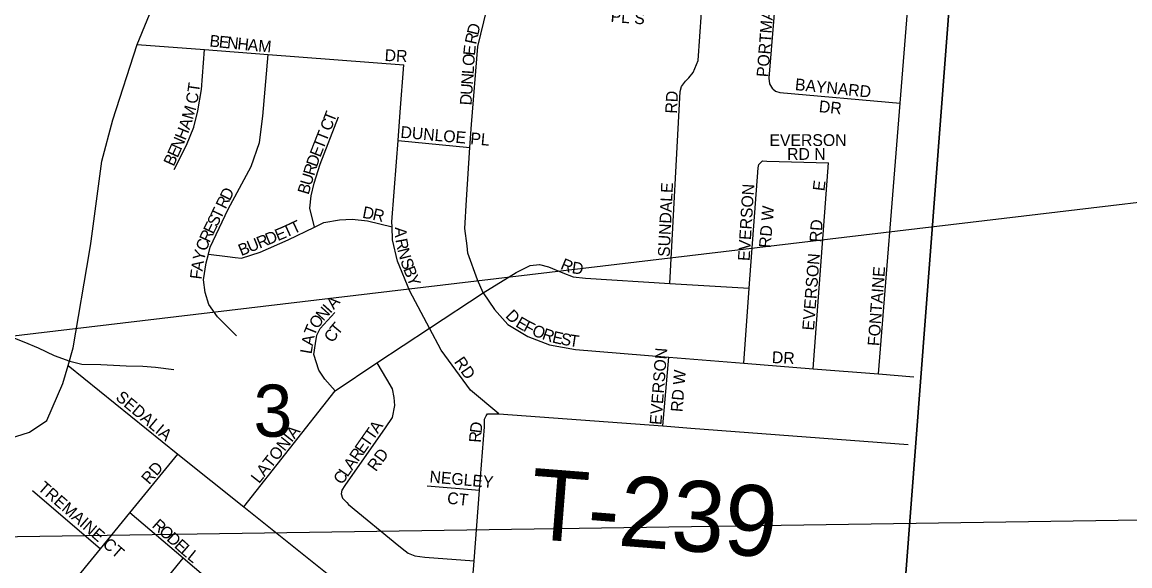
# Model space of a CAD drawing. Extents: x 0 to 34, y 0 to 22.
# Drawn here: x 7.534 to 8.423, y 17.345 to 17.781 of the extents above; entities that cross this region are included whole.
import ezdxf

# ---------------------------------------------------------------- set-up
doc = ezdxf.new("R2010")
doc.units = 0
for name, color, linetype in [('BD_P_Text', 7, 'Continuous'), ('GM_X_County_Road', 7, 'Continuous'), ('GM_X_Minor_River', 7, 'Continuous'), ('GM_X_Section', 7, 'Continuous'), ('GM_X_Section_Text', 7, 'Continuous'), ('GM_X_Township_Road', 7, 'Continuous'), ('GM_X_Township_Road_Text', 7, 'Continuous'), ('GM_X_Township_Subdivision', 7, 'Continuous'), ('GM_X_Township_Subdivision_Text', 7, 'Continuous')]:
    doc.layers.add(name, color=color, linetype=linetype)

msp = doc.modelspace()

# ---------------------------------------------------------------- linework, layer by layer
at = {"layer": 'BD_P_Text'}
msp.add_lwpolyline([(9.7485, 17.79308), (5.97867, 17.34543), (9.7485, 17.40141)], close=True, dxfattribs=at)
at = {"layer": 'GM_X_County_Road'}
for points in [[(7.58898, 17.60376), (7.58928, 17.60553), (7.59778, 17.66988), (7.6066, 17.70308), (7.62629, 17.76361), (7.65462, 17.83269), (7.66454, 17.86111), (7.67094, 17.88135), (7.67231, 17.90988)], [(7.20767, 17.30576), (7.22006, 17.35497), (7.22615, 17.36156), (7.23071, 17.36815), (7.2373, 17.37474), (7.25809, 17.39604), (7.28242, 17.41175), (7.30574, 17.42341), (7.34934, 17.43405), (7.48925, 17.44926), (7.52376, 17.44731), (7.53981, 17.45222), (7.55371, 17.46174), (7.56661, 17.49141), (7.57076, 17.5057), (7.57493, 17.52006), (7.58785, 17.59698), (7.58898, 17.60376)]]:
    msp.add_lwpolyline(points, dxfattribs=at)
at = {"layer": 'GM_X_Minor_River'}
msp.add_lwpolyline([(7.52385, 17.52935), (7.53517, 17.52472), (7.54686, 17.5201), (7.55968, 17.51395), (7.57213, 17.50932), (7.58195, 17.50698), (7.59707, 17.50651), (7.61749, 17.50563), (7.63072, 17.50517), (7.64092, 17.50435), (7.65566, 17.50274)], dxfattribs=at)
at = {"layer": 'GM_X_Section'}
for points in [[(7.25608, 17.99704), (7.7594, 17.95531), (8.26119, 17.91328), (8.28732, 17.91243), (8.21553, 16.97509), (7.19182, 17.04453)], [(8.28732, 17.91243), (8.78533, 17.87214), (9.29851, 17.83319), (9.21917, 16.9042), (8.21553, 16.97509)]]:
    msp.add_lwpolyline(points, close=True, dxfattribs=at)
at = {"layer": 'GM_X_Township_Road'}
for points in [[(7.91657, 17.46715), (8.04831, 17.45728), (8.0706, 17.45561), (8.0706, 17.45561)], [(8.0706, 17.45561), (8.24517, 17.44253)]]:
    msp.add_lwpolyline(points, dxfattribs=at)
at = {"layer": 'GM_X_Township_Subdivision'}
for points in [[(7.90411, 17.56419), (7.89935, 17.57452), (7.89173, 17.59591), (7.89107, 17.602), (7.8894, 17.6157), (7.89053, 17.63885), (7.89332, 17.68094), (7.89454, 17.69917), (7.89971, 17.76176), (7.90926, 17.80167), (7.92328, 17.84308), (7.945, 17.89819), (7.96341, 17.93943), (7.96608, 17.94542)], [(8.22144, 17.49905), (8.23877, 17.71644), (8.24732, 17.8237), (8.25217, 17.87646), (8.25174, 17.88662), (8.25005, 17.90439), (8.2509, 17.92059)], [(8.05394, 17.57175), (8.06211, 17.72575), (8.06332, 17.72991), (8.06642, 17.73403), (8.06912, 17.73665), (8.0726, 17.74115), (8.07654, 17.75059), (8.07937, 17.78927), (8.08318, 17.84124), (8.08626, 17.88336), (8.08428, 17.88993), (8.0845, 17.89175), (8.08145, 17.89996)], [(8.13644, 17.72798), (8.13423, 17.73181), (8.13355, 17.73638), (8.14576, 17.88279), (8.14694, 17.88543)], [(7.62629, 17.76361), (7.68026, 17.75946), (7.73133, 17.75552), (7.84035, 17.74714)], [(7.65592, 17.6631), (7.66571, 17.68269), (7.67163, 17.69704), (7.67488, 17.71028), (7.6778, 17.72732), (7.68026, 17.75946)], [(7.70608, 17.52976), (7.69078, 17.54481), (7.68374, 17.5548), (7.68086, 17.56434), (7.67951, 17.57461), (7.68162, 17.58825), (7.6834, 17.59511), (7.68485, 17.60074), (7.69938, 17.63127), (7.70837, 17.64821), (7.71774, 17.66553), (7.7245, 17.68479), (7.72711, 17.70602), (7.73133, 17.75552)], [(7.91657, 17.46715), (7.89375, 17.48612), (7.87039, 17.51802), (7.86089, 17.53579), (7.845, 17.56552), (7.83516, 17.5896), (7.83126, 17.60676), (7.83089, 17.61707), (7.83074, 17.6212), (7.83454, 17.66937), (7.83579, 17.68643), (7.83746, 17.7092), (7.84035, 17.74714)], [(8.13644, 17.72798), (8.13868, 17.72605), (8.14208, 17.72485), (8.23877, 17.71644)], [(7.76868, 17.6169), (7.76496, 17.63212), (7.76588, 17.64198), (7.76832, 17.65219), (7.77311, 17.66731), (7.78775, 17.70544)], [(7.83579, 17.68643), (7.89332, 17.68094)], [(8.11316, 17.50774), (8.11764, 17.56795), (8.1248, 17.66436), (8.12535, 17.6672), (8.12831, 17.67)], [(8.12831, 17.67), (8.13162, 17.66971), (8.18135, 17.6684)], [(8.16882, 17.50327), (8.18135, 17.6684)], [(7.6834, 17.59511), (7.69876, 17.5933), (7.70481, 17.59244), (7.71011, 17.59197), (7.72497, 17.59668), (7.74749, 17.60657), (7.76868, 17.6169), (7.77615, 17.62054), (7.78869, 17.62263), (7.79893, 17.62322), (7.81104, 17.62189), (7.83089, 17.61707)], [(7.7118, 17.39237), (7.78524, 17.48545), (7.81867, 17.50805), (7.86089, 17.53579), (7.90411, 17.56419), (7.93053, 17.58049), (7.9416, 17.586), (7.9492, 17.58702), (7.95637, 17.58501), (7.96804, 17.58027), (7.97633, 17.57709), (7.98617, 17.5758), (8.05394, 17.57175), (8.11764, 17.56795)], [(7.90411, 17.56419), (7.91299, 17.55076), (7.92379, 17.53882), (7.93993, 17.52906), (7.95726, 17.52232), (7.97804, 17.51858), (8.05298, 17.51256), (8.11316, 17.50774), (8.16882, 17.50327), (8.22144, 17.49905), (8.24984, 17.49677)], [(7.78524, 17.48545), (7.77677, 17.49482), (7.77196, 17.50212), (7.768, 17.51471), (7.76927, 17.52343), (7.77052, 17.53025), (7.77326, 17.53552), (7.78484, 17.54825)], [(8.04831, 17.45728), (8.05298, 17.51256)], [(7.57076, 17.5057), (7.65892, 17.43461), (7.7118, 17.39237), (7.80817, 17.3154), (7.83868, 17.29103), (7.84924, 17.28744), (7.89162, 17.28422), (8.17216, 17.26292), (8.1911, 17.26186), (8.20059, 17.26323), (8.21734, 17.26789), (8.22687, 17.27078), (8.23682, 17.27708), (8.2491, 17.28638), (8.25601, 17.29159), (8.26518, 17.29638), (8.2759, 17.30304), (8.29359, 17.31871)], [(7.81867, 17.50805), (7.82643, 17.49479), (7.83085, 17.48712), (7.83226, 17.48026), (7.83291, 17.4738), (7.83086, 17.46396), (7.82541, 17.45569), (7.79284, 17.4095), (7.7905, 17.40573), (7.79007, 17.4027), (7.79115, 17.39927), (7.79451, 17.3958), (7.796, 17.39425), (7.8364, 17.36094), (7.84127, 17.35707), (7.84389, 17.35513), (7.84916, 17.35314), (7.8571, 17.35188), (7.89665, 17.34891)], [(7.89162, 17.28422), (7.89665, 17.34891), (7.90108, 17.40585), (7.90503, 17.4567), (7.90513, 17.46277), (7.90631, 17.46541), (7.90747, 17.46691), (7.91657, 17.46715)], [(7.54485, 17.12154), (7.54917, 17.17842), (7.55737, 17.2864), (7.56025, 17.30079), (7.56361, 17.31139), (7.57168, 17.32795), (7.59686, 17.35873), (7.62042, 17.38754), (7.65892, 17.43461)], [(7.54223, 17.40551), (7.59686, 17.35873)], [(7.85916, 17.4092), (7.90108, 17.40585)], [(7.74685, 17.09652), (7.7516, 17.15869), (7.75502, 17.20349), (7.75477, 17.21147), (7.75156, 17.22368), (7.73097, 17.28667), (7.72842, 17.29316), (7.72135, 17.30163), (7.66326, 17.35108), (7.62042, 17.38754)], [(7.59917, 17.17384), (7.60832, 17.20241), (7.61036, 17.21188), (7.61286, 17.22551), (7.61551, 17.24863), (7.61792, 17.28087), (7.61995, 17.2892), (7.62427, 17.29863), (7.63083, 17.3087), (7.64176, 17.32493), (7.66326, 17.35108)]]:
    msp.add_lwpolyline(points, dxfattribs=at)

# ---------------------------------------------------------------- texts
at = {"layer": 'GM_X_Section_Text'}
msp.add_text('3', height=0.04186, rotation=0.00001, dxfattribs=at).set_placement((7.71965, 17.44863))
at = {"layer": 'GM_X_Township_Road_Text'}
msp.add_text('T-239', height=0.056818, rotation=355.5173, dxfattribs=at).set_placement((7.94, 17.36694))
at = {"layer": 'GM_X_Township_Subdivision_Text'}
for s, height, rotation, p in [('PORTMAN DR', 0.00947, 85.60129, (8.13287, 17.73704)), ('PL S', 0.00947, 355.76599, (8.00607, 17.7816)), ('D', 0.00947, 75.97147, (7.89992, 17.77034)), ('B', 0.00947, 354.06471, (7.684, 17.76197)), ('E', 0.00947, 354.04543, (7.69146, 17.7612)), ('N', 0.00947, 354.05611, (7.69809, 17.7605)), ('H', 0.00947, 354.05611, (7.70638, 17.75964)), ('A', 0.00947, 354.05611, (7.71467, 17.75878)), ('M', 0.00947, 355.0481, (7.72313, 17.7579)), ('R', 0.00947, 77.66285, (7.89833, 17.76308)), ('DR', 0.00947, 356.98842, (7.82474, 17.75031)), ('E', 0.00947, 84.4284, (7.89734, 17.75427)), ('O', 0.00947, 86.11978, (7.89678, 17.74603)), ('L', 0.00947, 86.11978, (7.89633, 17.73938)), ('CT', 0.00947, 81.87711, (7.67455, 17.71545)), ('U', 0.00947, 86.11978, (7.89521, 17.72275)), ('N', 0.00947, 86.11978, (7.89577, 17.73106)), ('BAYNARD', 0.00947, 354.20725, (8.15399, 17.72697)), ('D', 0.00947, 86.11978, (7.89464, 17.71444)), ('RD', 0.00947, 86.97755, (8.05953, 17.70783)), ('M', 0.00947, 73.53902, (7.67088, 17.70269)), ('DR', 0.00947, 353.99459, (8.17315, 17.70931)), ('T', 0.00947, 68.57406, (7.78418, 17.70034)), ('H', 0.00947, 67.96825, (7.6649, 17.68607)), ('A', 0.00947, 72.32694, (7.66828, 17.69454)), ('C', 0.00947, 68.5834, (7.78144, 17.69336)), ('DUNLOE PL', 0.00947, 354.80557, (7.83731, 17.68868)), ('N', 0.00947, 66.36465, (7.66144, 17.67817)), ('T', 0.00947, 68.57406, (7.77566, 17.67862)), ('T', 0.00947, 68.60243, (7.7781, 17.68483)), ('EVERSON', 0.00947, 0.00001, (8.13381, 17.68202)), ('E', 0.00947, 65.59595, (7.65863, 17.67197)), ('E', 0.00947, 68.69574, (7.77324, 17.67241)), ('RD N', 0.00947, 0.00001, (8.14798, 17.6709)), ('B', 0.00947, 65.58619, (7.65553, 17.66514)), ('D', 0.00947, 70.38293, (7.77047, 17.66463)), ('U', 0.00947, 73.23795, (7.76593, 17.64959)), ('R', 0.00947, 73.17047, (7.76833, 17.65757)), ('B', 0.00947, 73.24725, (7.76377, 17.64241)), ('SUNDALE', 0.00947, 87.35564, (8.05369, 17.59282)), ('E', 0.00947, 82.87834, (8.17788, 17.64545)), ('D', 0.00947, 63.84277, (7.70058, 17.63754)), ('EVERSON', 0.00947, 86.42557, (8.11787, 17.58951)), ('T', 0.00947, 63.85048, (7.69323, 17.62258)), ('R', 0.00947, 63.83384, (7.69727, 17.63081)), ('D', 0.00947, 348.98156, (7.80654, 17.6245)), ('RD W', 0.00947, 85.23886, (8.13477, 17.59988)), ('S', 0.00947, 63.85264, (7.69029, 17.6166)), ('R', 0.00947, 347.26571, (7.81465, 17.62293)), ('E', 0.00947, 63.82595, (7.68735, 17.61061)), ('E', 0.00947, 22.61411, (7.73916, 17.60558)), ('T', 0.00947, 24.47536, (7.74562, 17.60827)), ('T', 0.00947, 25.26923, (7.75181, 17.61109)), ('A', 0.00947, 271.61786, (7.8331, 17.61683)), ('RD', 0.00947, 86.05688, (8.17537, 17.60452)), ('C', 0.00947, 70.48991, (7.68179, 17.59701)), ('R', 0.00947, 65.03151, (7.68421, 17.60386)), ('U', 0.00947, 22.27918, (7.71674, 17.59639)), ('R', 0.00947, 22.27048, (7.72446, 17.59955)), ('D', 0.00947, 22.27359, (7.7314, 17.6024)), ('R', 0.00947, 280.84193, (7.83351, 17.60685)), ('Y', 0.00947, 75.79939, (7.67982, 17.58915)), ('B', 0.00947, 22.27048, (7.7098, 17.59355)), ('N', 0.00947, 284.40333, (7.83507, 17.59886)), ('A', 0.00947, 82.12951, (7.67873, 17.58117)), ('S', 0.00947, 289.15611, (7.83739, 17.58996)), ('R', 0.00947, 337.44552, (7.96537, 17.58352)), ('D', 0.00947, 351.51534, (7.9747, 17.57998)), ('EVERSON', 0.00947, 85.53522, (8.16954, 17.53371)), ('F', 0.00947, 82.631, (7.67787, 17.57458)), ('B', 0.00947, 290.99095, (7.83969, 17.58336)), ('FONTAINE', 0.00947, 85.79698, (8.22204, 17.5212)), ('Y', 0.00947, 291.1506, (7.84238, 17.57632)), ('N', 0.00947, 48.3719, (7.77576, 17.54095)), ('I', 0.00947, 48.12325, (7.78128, 17.54717)), ('A', 0.00947, 48.12493, (7.78406, 17.55027)), ('O', 0.00947, 52.05024, (7.77073, 17.5345)), ('D', 0.00947, 314.2736, (7.92134, 17.54515)), ('E', 0.00947, 329.7623, (7.92936, 17.53746)), ('T', 0.00947, 67.87394, (7.76857, 17.52892)), ('T', 0.00947, 50.02999, (7.78733, 17.52947)), ('F', 0.00947, 332.68919, (7.93558, 17.53385)), ('O', 0.00947, 338.42415, (7.94244, 17.53037)), ('R', 0.00947, 340.95987, (7.95062, 17.52714)), ('A', 0.00947, 80.41043, (7.76733, 17.52123)), ('C', 0.00947, 55.95297, (7.78329, 17.52346)), ('E', 0.00947, 347.38739, (7.95883, 17.52438)), ('S', 0.00947, 349.21676, (7.96566, 17.52286)), ('T', 0.00947, 351.34475, (7.97258, 17.52154)), ('L', 0.00947, 80.39396, (7.76621, 17.51465)), ('EVERSON', 0.00947, 85.53182, (8.04704, 17.45787)), ('RD', 0.00947, 304.50795, (7.88028, 17.50874)), ('DR', 0.00947, 356.98902, (8.13557, 17.50784)), ('RD W', 0.00947, 85.23283, (8.06393, 17.46821)), ('SEDALIA', 0.00947, 319.82096, (7.6083, 17.4791)), ('LATONIA', 0.00947, 51.62901, (7.72408, 17.41051)), ('T', 0.00947, 54.99902, (7.81555, 17.44508)), ('A', 0.00947, 55.42241, (7.81941, 17.45061)), ('D', 0.00947, 82.72315, (7.90257, 17.451)), ('T', 0.00947, 54.98964, (7.81172, 17.43962)), ('R', 0.00947, 85.81921, (7.90203, 17.44365)), ('R', 0.00947, 54.99529, (7.8036, 17.42802)), ('E', 0.00947, 54.99902, (7.8079, 17.43416)), ('RD', 0.00947, 53.7411, (7.81787, 17.42009)), ('A', 0.00947, 55.00095, (7.79882, 17.4212)), ('RD', 0.00947, 49.0906, (7.63583, 17.40971)), ('C', 0.00947, 55.00996, (7.79069, 17.40959)), ('L', 0.00947, 54.98335, (7.79499, 17.41574)), ('NEGLEY', 0.00947, 354.89673, (7.86064, 17.41201)), ('TREMAINE CT', 0.0094697, 318.92967, (7.54582, 17.40658)), ('CT', 0.00947, 353.65048, (7.87471, 17.39498)), ('R', 0.00947, 317.83411, (7.63751, 17.37656)), ('O', 0.00947, 317.8539, (7.64307, 17.37152)), ('D', 0.00947, 317.82922, (7.64925, 17.36593)), ('E', 0.00947, 317.8484, (7.65543, 17.36033)), ('L', 0.00947, 319.05256, (7.66053, 17.35572)), ('L', 0.00947, 320.96434, (7.66583, 17.35113))]:
    msp.add_text(s, height=height, rotation=rotation, dxfattribs=at).set_placement(p)

doc.saveas('drawing.dxf')
